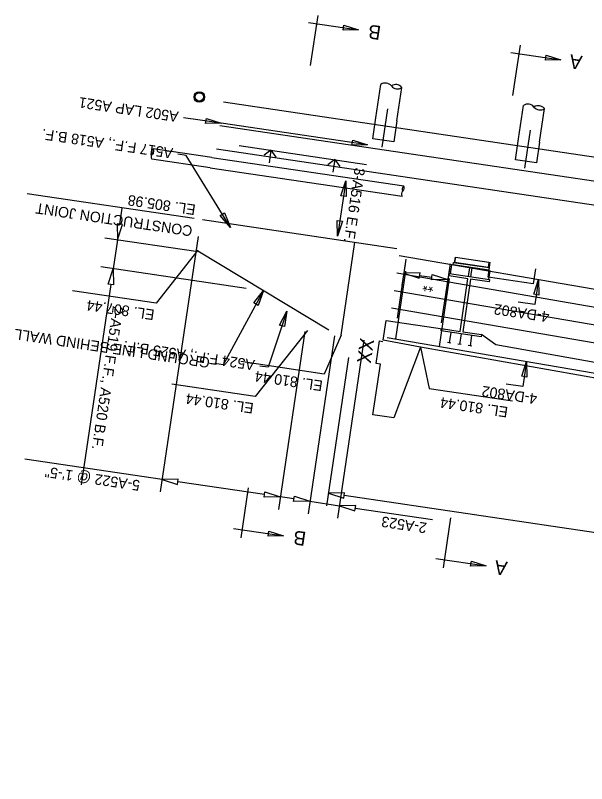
# Model space of a CAD drawing. Extents: x 1467956 to 1469946, y 573734 to 574139.
# Drawn here: x 1468962.44 to 1468989.52, y 574056.5 to 574092.91 of the extents above; entities that cross this region are included whole.
import ezdxf

# ---------------------------------------------------------------- set-up
doc = ezdxf.new("R2010")
doc.units = 0
for name, color, linetype in [('BR_P_Beam_Object', 7, 'Continuous'), ('BR_P_Beam_Stl_Det_Hidden', 7, 'Continuous'), ('BR_P_Brg_Pad_Object', 7, 'Continuous'), ('BR_P_Dia_Hidden', 7, 'Continuous'), ('BR_P_Dia_Reinforcing', 7, 'Continuous'), ('BR_P_Gen_NonPerf_Pipe', 7, 'Continuous'), ('BR_P_Gen_Text', 7, 'Continuous'), ('BR_P_Rail_Const_Joint', 7, 'Continuous'), ('BR_P_Slab_Object', 7, 'Continuous'), ('BR_P_Sub_Const_Joint', 7, 'Continuous'), ('BR_P_Sub_Deep_Centerline', 7, 'Continuous'), ('BR_P_Sub_Deep_Hidden', 7, 'Continuous'), ('BR_P_Sub_Deep_Object', 7, 'Continuous'), ('BR_P_Sub_Foot_Reinforcing', 7, 'Continuous'), ('BR_P_Sub_Hidden', 7, 'Continuous'), ('BR_P_Sub_Text', 7, 'Continuous'), ('Default', 7, 'Continuous')]:
    doc.layers.add(name, color=color, linetype=linetype)

# ---------------------------------------------------------------- blocks, each defined once
blk = doc.blocks.new('arrowOhio')
at = {"layer": 'Default'}
blk.add_lwpolyline([(0.00381, 0.000635), (0.00381, -0.000635), (0, 0)], close=True, dxfattribs=at)

msp = doc.modelspace()

# ---------------------------------------------------------------- linework, layer by layer
at = {"layer": 'BR_P_Beam_Object'}
for p, q in [((1468983.004, 574080.558), (1468983.021, 574080.671)), ((1468983.892, 574080.426), (1468983.004, 574080.558)), ((1468983.021, 574080.671), (1468984.917, 574080.39)), ((1468983.523, 574077.932), (1468983.892, 574080.426)), ((1468984.012, 574080.408), (1468983.643, 574077.915)), ((1468984.9, 574080.277), (1468984.012, 574080.408)), ((1468984.917, 574080.39), (1468984.9, 574080.277)), ((1468982.618, 574077.951), (1468982.635, 574078.064)), ((1468984.514, 574077.67), (1468982.618, 574077.951)), ((1468982.635, 574078.064), (1468983.523, 574077.932)), ((1468983.071, 574077.884), (1468982.998, 574077.389)), ((1468983.643, 574077.915), (1468984.531, 574077.783)), ((1468983.566, 574077.81), (1468983.493, 574077.316)), ((1468984.061, 574077.737), (1468983.987, 574077.242)), ((1468984.531, 574077.783), (1468984.514, 574077.67)), ((1468983.081, 574077.377), (1468982.916, 574077.401)), ((1468983.575, 574077.303), (1468983.41, 574077.328)), ((1468984.07, 574077.23), (1468983.905, 574077.255))]:
    msp.add_line(p, q, dxfattribs=at)
at = {"layer": 'BR_P_Beam_Stl_Det_Hidden'}
for p, q in [((1468983.062, 574080.665), (1468983.124, 574081.087)), ((1468983.909, 574080.539), (1468983.972, 574080.962)), ((1468984.028, 574080.522), (1468984.091, 574080.944)), ((1468984.876, 574080.396), (1468984.938, 574080.819))]:
    msp.add_line(p, q, dxfattribs=at)
at = {"layer": 'BR_P_Brg_Pad_Object'}
for p, q in [((1468983.188, 574081.078), (1468983.206, 574081.202)), ((1468983.206, 574081.202), (1468984.893, 574080.952)), ((1468983.294, 574081.452), (1468983.256, 574081.194)), ((1468984.882, 574081.217), (1468984.843, 574080.959)), ((1468984.875, 574080.828), (1468983.188, 574081.078)), ((1468984.893, 574080.952), (1468984.875, 574080.828))]:
    msp.add_line(p, q, dxfattribs=at)
msp.add_lwpolyline([(1468984.882, 574081.217), (1468984.843, 574080.959), (1468983.256, 574081.194), (1468983.294, 574081.452)], close=True, dxfattribs=at)
at = {"layer": 'BR_P_Dia_Hidden'}
msp.add_line((1468977.874, 574077.746), (1468978.527, 574082.158), dxfattribs=at)
at = {"layer": 'BR_P_Dia_Reinforcing'}
for p, q in [((1468980.635, 574081.53), (1468997.15, 574078.687)), ((1468980.947, 574081.36), (1468980.531, 574078.553)), ((1468983.043, 574081.14), (1468982.627, 574078.332)), ((1468980.47, 574077.573), (1468980.946, 574080.788)), ((1468980.512, 574080.703), (1468997.027, 574077.86)), ((1468982.546, 574077.216), (1468983.022, 574080.431)), ((1468980.39, 574079.875), (1468996.905, 574077.032)), ((1468980.267, 574079.048), (1468996.782, 574076.205)), ((1468980.059, 574077.644), (1468996.575, 574074.801))]:
    msp.add_line(p, q, dxfattribs=at)
at = {"layer": 'BR_P_Gen_NonPerf_Pipe'}
for p, q in [((1468971.743, 574086.174), (1468968.973, 574086.585)), ((1468971.669, 574085.68), (1468968.9, 574086.09))]:
    msp.add_line(p, q, dxfattribs=at)
for radius in [0.25, 0.2]:
    msp.add_circle((1468971.156, 574089.041), radius, dxfattribs=at)
for centre, start, end in [((1468969.084, 574086.442), 127.976, 215.1816), ((1468968.825, 574086.48), 307.976, 35.1816), ((1468969.048, 574086.194), 127.976, 215.1816)]:
    msp.add_arc(centre, 0.181, start, end, dxfattribs=at)
at = {"layer": 'BR_P_Gen_Text'}
for p, q in [((1468971.195, 574087.94), (1468970.404, 574088.057)), ((1468972.193, 574087.793), (1468971.195, 574087.94)), ((1468972.193, 574087.793), (1468972.193, 574087.793)), ((1468979.13, 574086.766), (1468972.193, 574087.793)), ((1468970.539, 574086.269), (1468970.143, 574086.328)), ((1468972.634, 574082.862), (1468970.539, 574086.269)), ((1468978.099, 574085.065), (1468977.711, 574082.447)), ((1468967.389, 574083.016), (1468967.501, 574083.768)), ((1468970.997, 574081.713), (1468966.684, 574082.352)), ((1468967.278, 574082.264), (1468967.076, 574080.903)), ((1468971.094, 574082.427), (1468969.301, 574070.321)), ((1468971.092, 574081.782), (1468969.104, 574079.275)), ((1468980.911, 574081.123), (1468980.76, 574080.099)), ((1468973.38, 574079.97), (1468966.483, 574080.991)), ((1468983.008, 574080.902), (1468982.843, 574079.79)), ((1468981.599, 574080.581), (1468982.179, 574080.495)), ((1468987.241, 574080.393), (1468987.065, 574079.206)), ((1468966.965, 574080.151), (1468965.56, 574070.66)), ((1468969.104, 574079.275), (1468965.147, 574079.861)), ((1468974.193, 574079.862), (1468972.29, 574076.344)), ((1468987.065, 574079.206), (1468986.274, 574079.323)), ((1468975.301, 574078.886), (1468974.417, 574076.229)), ((1468976.289, 574077.98), (1468973.804, 574074.846)), ((1468976.156, 574077.926), (1468974.907, 574069.491)), ((1468977.557, 574077.718), (1468976.308, 574069.284)), ((1468977.874, 574077.746), (1468977.079, 574075.91)), ((1468978.958, 574077.511), (1468977.71, 574069.076)), ((1468981.648, 574077.187), (1468982.05, 574075.228)), ((1468972.29, 574076.344), (1468971.894, 574076.402)), ((1468977.079, 574075.91), (1468973.122, 574076.496)), ((1468978.226, 574076.7), (1468977.186, 574069.669)), ((1468986.665, 574076.507), (1468986.49, 574075.32)), ((1468974.417, 574076.229), (1468974.021, 574076.288)), ((1468973.804, 574074.846), (1468969.847, 574075.432)), ((1468986.49, 574075.32), (1468985.698, 574075.437)), ((1468982.05, 574075.228), (1468986.007, 574074.642)), ((1468969.389, 574070.915), (1468962.882, 574071.878)), ((1468974.243, 574070.196), (1468970.141, 574070.803)), ((1468975.644, 574069.989), (1468974.893, 574070.1)), ((1468976.396, 574069.877), (1468977.798, 574069.67)), ((1469070.259, 574056.497), (1468978.025, 574070.152)), ((1468978.549, 574069.559), (1468982.202, 574069.018))]:
    msp.add_line(p, q, dxfattribs=at)
for points in [[(1468967.515, 574082.997), (1468967.264, 574083.034), (1468967.278, 574082.264)], [(1468967.09, 574080.133), (1468966.84, 574080.17), (1468967.076, 574080.903)], [(1468981.581, 574080.456), (1468981.618, 574080.706), (1468980.848, 574080.692)], [(1468982.161, 574080.37), (1468982.198, 574080.621), (1468982.931, 574080.384)], [(1468970.123, 574070.678), (1468970.16, 574070.929), (1468969.389, 574070.915)], [(1468974.224, 574070.071), (1468974.262, 574070.321), (1468974.995, 574070.085)], [(1468978.007, 574070.026), (1468978.044, 574070.277), (1468977.273, 574070.263)], [(1468975.626, 574069.863), (1468975.663, 574070.114), (1468976.396, 574069.877)], [(1468978.531, 574069.433), (1468978.568, 574069.684), (1468977.798, 574069.67)]]:
    msp.add_lwpolyline(points, close=True, dxfattribs=at)
at = {"layer": 'BR_P_Rail_Const_Joint'}
msp.add_line((1468981.648, 574077.187), (1468979.871, 574077.508), dxfattribs=at)
at = {"layer": 'BR_P_Slab_Object'}
for p, q in [((1468979.871, 574077.508), (1468980.011, 574078.452)), ((1468980.011, 574078.452), (1468982.795, 574078.04)), ((1468979.539, 574076.404), (1468979.698, 574077.476)), ((1468979.698, 574077.476), (1468979.862, 574077.451)), ((1468981.648, 574077.187), (1468980.376, 574073.837)), ((1468981.648, 574077.187), (1468981.648, 574077.187)), ((1468981.648, 574077.187), (1468981.648, 574077.187)), ((1469026.696, 574069.14), (1468981.648, 574077.187)), ((1468979.737, 574076.375), (1468979.539, 574076.404)), ((1468979.383, 574073.984), (1468979.737, 574076.375)), ((1468980.376, 574073.837), (1468979.383, 574073.984))]:
    msp.add_line(p, q, dxfattribs=at)
msp.add_lwpolyline([(1468993.612, 574076.105), (1468992.828, 574075.93), (1468985.216, 574077.29), (1468984.531, 574077.783)], dxfattribs=at)
at = {"layer": 'BR_P_Sub_Const_Joint'}
msp.add_line((1468971.306, 574083.227), (1468980.516, 574081.863), dxfattribs=at)
at = {"layer": 'BR_P_Sub_Deep_Centerline'}
for p, q in [((1468979.831, 574086.662), (1468980.099, 574088.475)), ((1468986.59, 574085.661), (1468986.859, 574087.475))]:
    msp.add_line(p, q, dxfattribs=at)
at = {"layer": 'BR_P_Sub_Deep_Hidden'}
for p, q in [((1468979.385, 574087.065), (1468979.531, 574088.054)), ((1468980.52, 574087.908), (1468980.374, 574086.918)), ((1468980.374, 574086.918), (1468979.385, 574087.065)), ((1468986.144, 574086.064), (1468986.291, 574087.053)), ((1468987.28, 574086.907), (1468987.134, 574085.918)), ((1468987.134, 574085.918), (1468986.144, 574086.064))]:
    msp.add_line(p, q, dxfattribs=at)
at = {"layer": 'BR_P_Sub_Deep_Object'}
for p, q in [((1468979.531, 574088.054), (1468979.766, 574089.637)), ((1468980.52, 574087.908), (1468980.755, 574089.49)), ((1468986.291, 574087.053), (1468986.525, 574088.636)), ((1468987.28, 574086.907), (1468987.514, 574088.49))]:
    msp.add_line(p, q, dxfattribs=at)
for centre, start, end in [((1468979.974, 574089.341), 37.976, 125.1816), ((1468980.469, 574089.267), 37.976, 125.1816), ((1468980.546, 574089.787), 217.976, 305.1816), ((1468986.734, 574088.34), 37.976, 125.1816), ((1468987.229, 574088.267), 37.976, 125.1816), ((1468987.306, 574088.786), 217.976, 305.1816)]:
    msp.add_arc(centre, 0.362, start, end, dxfattribs=at)
at = {"layer": 'BR_P_Sub_Foot_Reinforcing'}
for p, q in [((1468976.432, 574090.535), (1468976.783, 574092.909)), ((1468976.329, 574092.572), (1468978.703, 574092.22)), ((1468986.025, 574089.115), (1468986.377, 574091.489)), ((1468985.922, 574091.152), (1468988.296, 574090.8)), ((1469004.297, 574084.051), (1468972.298, 574088.788)), ((1469010.688, 574081.967), (1468972.133, 574087.675)), ((1469010.523, 574080.854), (1468971.968, 574086.562)), ((1468973.468, 574070.513), (1468973.116, 574068.139)), ((1468983.061, 574069.093), (1468982.709, 574066.719)), ((1468972.779, 574068.593), (1468975.153, 574068.242)), ((1468982.372, 574067.173), (1468984.746, 574066.821))]:
    msp.add_line(p, q, dxfattribs=at)
at = {"layer": 'BR_P_Sub_Hidden'}
for p, q in [((1468971.743, 574086.174), (1468980.843, 574084.827)), ((1468971.669, 574085.68), (1468980.77, 574084.333)), ((1468977.303, 574077.995), (1468971.084, 574081.728))]:
    msp.add_line(p, q, dxfattribs=at)
for centre, start, end in [((1468980.955, 574084.684), 127.976, 215.1816), ((1468980.695, 574084.723), 307.976, 35.1816), ((1468980.918, 574084.437), 127.976, 215.1816)]:
    msp.add_arc(centre, 0.181, start, end, dxfattribs=at)
at = {"layer": 'BR_P_Sub_Text'}
for p, q in [((1468973.039, 574086.741), (1468979.083, 574085.846)), ((1468974.55, 574086.517), (1468974.229, 574086.279)), ((1468974.55, 574086.517), (1468974.463, 574085.923)), ((1468974.55, 574086.517), (1468974.789, 574086.196)), ((1468977.572, 574086.07), (1468977.251, 574085.831)), ((1468977.572, 574086.07), (1468977.485, 574085.476)), ((1468977.572, 574086.07), (1468977.811, 574085.748)), ((1468970.91, 574083.285), (1468962.997, 574084.457))]:
    msp.add_line(p, q, dxfattribs=at)
msp.add_lwpolyline([(1468987.091, 574080.89), (1468986.986, 574080.179), (1468984.843, 574080.496), (1468984.948, 574081.207)], dxfattribs=at)

# ---------------------------------------------------------------- block references
at = {"layer": 'BR_P_Gen_Text'}
for p, xscale, yscale, rotation in [((1468972.193, 574087.793), 191.49568000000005, 191.49568, 171.57876932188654), ((1468979.13, 574086.766), 191.49568000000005, 191.49568, 171.57876932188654), ((1468978.099, 574085.065), 191.49568000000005, 191.49568, -98.42123067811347), ((1468972.634, 574082.862), 191.49568, 191.49568, 121.57876932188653), ((1468977.711, 574082.447), 191.49568000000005, 191.49568, 81.57876932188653), ((1468987.241, 574080.393), 191.49568000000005, 191.49568, -98.42123067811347), ((1468974.193, 574079.862), 191.49568000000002, 191.49567999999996, -118.42123067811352), ((1468975.301, 574078.886), 191.49568000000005, 191.49568000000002, -108.42123067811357), ((1468986.665, 574076.507), 191.49568000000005, 191.49568, -98.42123067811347)]:
    msp.add_blockref('arrowOhio', p, dxfattribs=dict(at, xscale=xscale, yscale=yscale, rotation=rotation))
at = {"layer": 'BR_P_Sub_Foot_Reinforcing', "xscale": 188.97600000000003, "yscale": 188.97599999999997, "rotation": 171.57876932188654}
for p in [(1468978.703, 574092.22), (1468988.296, 574090.8), (1468975.153, 574068.242), (1468984.746, 574066.821)]:
    msp.add_blockref('arrowOhio', p, dxfattribs=at)

# ---------------------------------------------------------------- texts
at = {"layer": 'BR_P_Gen_Text'}
for s, height, rotation, p in [('B', 0.665, 171.5788, (1468979.802, 574092.394)), ('A', 0.665, 171.5788, (1468989.341, 574090.981)), ('A502 LAP A521', 0.5, 171.5788, (1468970.193, 574088.341)), ('A517 F.F., A518 B.F.', 0.5, 171.5788, (1468969.933, 574086.612)), ('3-A516 E.F.', 0.5, 261.5788, (1468978.524, 574085.715)), ('EL. 805.98', 0.5, 171.5788, (1468971.006, 574083.932)), ('CONSTRUCTION JOINT', 0.5, 171.5788, (1468970.857, 574082.923)), ('**', 0.5, 171.5788, (1468982.301, 574080.275)), ('EL. 807.44', 0.5, 171.5788, (1468969.056, 574078.953)), ('2-A519 F.F., A520 B.F.', 0.5, 261.5788, (1468967.062, 574079.157)), ('4-DA802', 0.5, 171.5788, (1468987.774, 574078.853)), ('GROUND LINE BEHIND WALL', 0.5, 171.5788, (1468971.683, 574076.686)), ('A524 F.F., A525 B.F.', 0.5, 171.5788, (1468973.81, 574076.572)), ('XX', 0.665, 261.5788, (1468978.792, 574077.644)), ('EL. 810.44', 0.5, 171.5788, (1468977.031, 574075.588)), ('4-DA802', 0.5, 171.5788, (1468987.199, 574074.966)), ('EL. 810.44', 0.5, 171.5788, (1468973.756, 574074.524)), ('EL. 810.44', 0.5, 171.5788, (1468985.813, 574074.341)), ('5-A522 @ 1\'-5"', 0.5, 171.5788, (1468968.371, 574070.863)), ('2-A523', 0.5, 171.5788, (1468981.963, 574068.851)), ('B', 0.665, 171.5788, (1468976.252, 574068.415)), ('A', 0.665, 171.5788, (1468985.791, 574067.003))]:
    msp.add_text(s, height=height, rotation=rotation, dxfattribs=at).set_placement(p)

doc.saveas('drawing.dxf')
